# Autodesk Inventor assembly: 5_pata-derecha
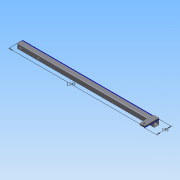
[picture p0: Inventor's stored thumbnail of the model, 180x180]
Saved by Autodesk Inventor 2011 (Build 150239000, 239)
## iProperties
Created: 2020-12
Part Number: 5_pata-derecha
Document SubType Name: Assembly
Designer: PC
Mass: 8098.06 g
Surface Area: 4945.21 cm^2
Volume: 1030.29 cm^3
Density: 7.86 g/cm^3
_SolveAssemblyDoc: Frame Generator Solve Assembly
_Version: 15.0.0
Author: PC
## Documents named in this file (3)
- C:\Users\PC\Documents\Inventor\workshop-crane-powered-by-drill\5_pata-derecha.iam
- C:\Users\PC\Documents\Inventor\workshop-crane-powered-by-drill\5_pata-derecha_esqueleto.ipt
- C:\Users\PC\Documents\Inventor\workshop-crane-powered-by-drill\5_pata-derecha\Frame\Frame0001.iam
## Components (2 placed, 2 different names)
1. 5_pata-derecha_esqueleto:1
2. Frame0001:1 [sub-assembly]
